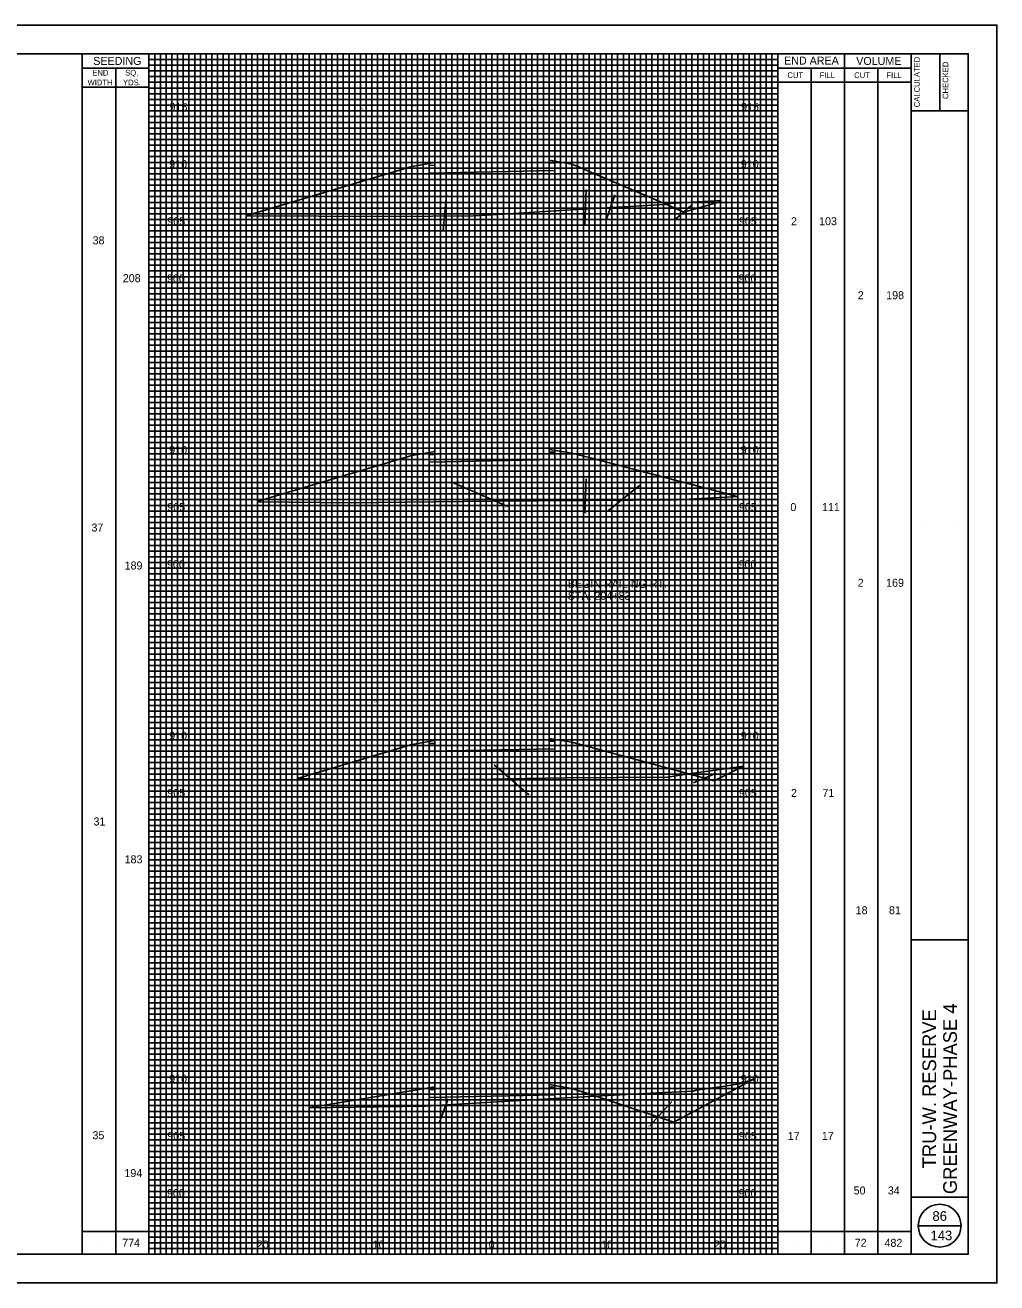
# Model space of a CAD drawing. Extents: x -73 to 160, y -2 to 1877.
# Drawn here: x 75 to 160, y 1377.5 to 1487.5 of the extents above; entities that cross this region are included whole.
import ezdxf

# ---------------------------------------------------------------- set-up
doc = ezdxf.new("R2010")
doc.units = 0
for name, color, linetype in [('DR_P_Flood_Boundary', 7, 'Continuous'), ('GK_Cells', 7, 'Continuous'), ('RD_X_Fence', 7, 'Continuous'), ('TX_X_5', 7, 'Continuous'), ('UT_P_Water_Cells', 7, 'Continuous'), ('XS_P_Pavt_Layers', 7, 'Continuous'), ('XS_P_Pavt_Surface', 7, 'Continuous'), ('XS_X_Ground_Line', 7, 'Continuous')]:
    doc.layers.add(name, color=color, linetype=linetype)

msp = doc.modelspace()

# ---------------------------------------------------------------- linework, layer by layer
at = {"layer": 'DR_P_Flood_Boundary'}
for p, q in [((90.83, 1380), (90.83, 1485)), ((95.83, 1380), (95.83, 1485)), ((100.83, 1380), (100.83, 1485)), ((105.83, 1380), (105.83, 1485)), ((110.83, 1380), (110.83, 1485)), ((115.83, 1380), (115.83, 1485)), ((120.83, 1380), (120.83, 1485)), ((125.83, 1380), (125.83, 1485)), ((130.83, 1380), (130.83, 1485)), ((135.83, 1380), (135.83, 1485)), ((85.83, 1480), (140.83, 1480)), ((85.83, 1475), (140.83, 1475)), ((85.83, 1470), (140.83, 1470)), ((85.83, 1465), (140.83, 1465)), ((85.83, 1460), (140.83, 1460)), ((85.83, 1455), (140.83, 1455)), ((85.83, 1450), (140.83, 1450)), ((85.83, 1445), (140.83, 1445)), ((85.83, 1440), (140.83, 1440)), ((85.83, 1435), (140.83, 1435)), ((85.83, 1430), (140.83, 1430)), ((85.83, 1425), (140.83, 1425)), ((85.83, 1420), (140.83, 1420)), ((85.83, 1415), (140.83, 1415)), ((85.83, 1410), (140.83, 1410)), ((85.83, 1405), (140.83, 1405)), ((85.83, 1400), (140.83, 1400)), ((85.83, 1395), (140.83, 1395)), ((85.83, 1390), (140.83, 1390)), ((85.83, 1385), (140.83, 1385))]:
    msp.add_line(p, q, dxfattribs=at)
at = {"layer": 'GK_Cells'}
for p, q in [((152.5, 1380), (152.5, 1485)), ((155, 1485), (155, 1480)), ((152.5, 1480), (157.5, 1480)), ((152.5, 1407.5), (157.5, 1407.5)), ((152.5, 1385), (157.5, 1385))]:
    msp.add_line(p, q, dxfattribs=at)
msp.add_lwpolyline([(0, 1485), (157.5, 1485), (157.5, 1380), (0, 1380)], close=True, dxfattribs=at)
at = {"layer": 'RD_X_Fence'}
for p, q in [((108.83, 1475.15), (94.31, 1470.83)), ((110.83, 1475.49), (108.83, 1475.15)), ((110.33, 1475.23), (110.83, 1475.24)), ((110.33, 1474.56), (110.33, 1475.23)), ((122.83, 1475.35), (120.83, 1475.69)), ((120.83, 1475.44), (121.33, 1475.45)), ((121.33, 1475.45), (121.33, 1474.78)), ((123.83, 1474.92), (122.83, 1475.35)), ((121.33, 1474.78), (110.33, 1474.56)), ((123.83, 1471.4), (123.83, 1474.92)), ((124.33, 1474.71), (123.83, 1474.92)), ((123.83, 1474.92), (123.83, 1471.4)), ((124.33, 1471.43), (124.33, 1474.71)), ((130.98, 1471.86), (124.33, 1474.71)), ((124.33, 1474.71), (124.33, 1471.43)), ((124.08, 1473.12), (123.97, 1469.99)), ((111.86, 1472.69), (111.57, 1469.54)), ((124.33, 1471.43), (130.99, 1471.8)), ((126.59, 1472.65), (125.85, 1470.54)), ((135.84, 1472.16), (130.98, 1471.86)), ((130.98, 1471.86), (132.63, 1471.15)), ((132.63, 1471.15), (135.87, 1472.07)), ((123.83, 1471.4), (124.33, 1471.43)), ((133.27, 1471.73), (131.93, 1470.57)), ((108.83, 1449.87), (95.37, 1445.86)), ((110.83, 1450.2), (108.83, 1449.87)), ((110.33, 1449.94), (110.83, 1449.95)), ((110.33, 1449.28), (110.33, 1449.94)), ((122.83, 1450.07), (120.83, 1450.4)), ((120.83, 1450.15), (121.33, 1450.16)), ((121.33, 1450.16), (121.33, 1449.5)), ((123.83, 1449.81), (122.83, 1450.07)), ((123.83, 1445.92), (123.83, 1449.81)), ((124.33, 1449.68), (123.83, 1449.81)), ((123.83, 1449.81), (123.83, 1445.92)), ((121.33, 1449.5), (110.33, 1449.28)), ((124.33, 1445.92), (124.33, 1449.68)), ((137.27, 1446.28), (124.33, 1449.68)), ((124.33, 1449.68), (124.33, 1445.92)), ((124.08, 1447.83), (123.97, 1444.81)), ((112.32, 1447.53), (117.22, 1445.41)), ((128.75, 1447.24), (126.04, 1445.06)), ((123.83, 1445.92), (124.33, 1445.92)), ((124.33, 1445.92), (132.05, 1445.98)), ((132.05, 1445.98), (137.27, 1446.28)), ((108.83, 1424.59), (98.83, 1421.61)), ((110.83, 1424.92), (108.83, 1424.59)), ((110.33, 1424.66), (110.83, 1424.67)), ((110.33, 1424), (110.33, 1424.66)), ((122.83, 1424.79), (120.83, 1425.12)), ((120.83, 1424.87), (121.33, 1424.88)), ((121.33, 1424.88), (121.33, 1424.22)), ((133.05, 1422.01), (122.83, 1424.79)), ((121.33, 1424.22), (110.33, 1424)), ((116.03, 1422.81), (119.05, 1420.18)), ((137.83, 1422.7), (133.05, 1422.01)), ((135.26, 1421.41), (137.83, 1422.7)), ((133.05, 1422.01), (135.26, 1421.41)), ((135.38, 1422.04), (133.45, 1421.22)), ((122.83, 1394.51), (120.83, 1394.85)), ((131.75, 1391.54), (138.83, 1395.37)), ((110.83, 1394.65), (99.79, 1392.8)), ((110.33, 1394.39), (110.83, 1394.4)), ((110.33, 1393.72), (110.33, 1394.39)), ((121.33, 1393.94), (110.33, 1393.72)), ((120.83, 1394.6), (121.33, 1394.61)), ((121.33, 1394.61), (121.33, 1393.94)), ((124.92, 1393.82), (122.83, 1394.51)), ((124.92, 1393.82), (131.75, 1391.54)), ((112.01, 1393.58), (111.25, 1391.54)), ((131.56, 1393.36), (129.63, 1391.24))]:
    msp.add_line(p, q, dxfattribs=at)
for points in [[(110.83, 1475.24), (110.83, 1475.38), (110.83, 1475.49)], [(120.83, 1475.69), (120.83, 1475.58), (120.83, 1475.44)], [(130.99, 1471.8), (130.98, 1471.86)], [(135.87, 1472.07), (135.84, 1472.16)], [(94.31, 1470.83), (107.04, 1470.75), (114.22, 1470.83), (115.83, 1470.92), (121.43, 1471.27), (123.83, 1471.4)], [(110.83, 1449.95), (110.83, 1450.1), (110.83, 1450.2)], [(120.83, 1450.4), (120.83, 1450.3), (120.83, 1450.15)], [(95.37, 1445.86), (95.39, 1445.8)], [(95.39, 1445.8), (103.51, 1445.73), (110.75, 1445.82), (115.83, 1445.86), (123.83, 1445.92)], [(110.83, 1424.67), (110.83, 1424.82), (110.83, 1424.92)], [(120.83, 1425.12), (120.83, 1425.02), (120.83, 1424.87)], [(98.83, 1421.61), (104.77, 1421.44), (115.83, 1421.56), (117.1, 1421.58), (122.27, 1421.67), (131.19, 1421.74), (133.05, 1422.01)], [(120.83, 1394.85), (120.83, 1394.74), (120.83, 1394.6)], [(138.83, 1395.37), (137.7, 1394.93), (136.2, 1394.7), (133.69, 1394.34), (133.45, 1394.27), (129.74, 1394.09), (124.92, 1393.82)], [(99.79, 1392.8), (110.03, 1392.96), (115.83, 1393.29), (124.92, 1393.82)], [(110.83, 1394.4), (110.83, 1394.54), (110.83, 1394.65)]]:
    msp.add_lwpolyline(points, dxfattribs=at)
at = {"layer": 'TX_X_5'}
msp.add_lwpolyline([(-10, 1377.5), (160, 1377.5), (160, 1487.5), (-10, 1487.5)], close=True, dxfattribs=at)
at = {"layer": 'UT_P_Water_Cells'}
for p, q in [((86.33, 1380), (86.33, 1485)), ((86.83, 1380), (86.83, 1485)), ((87.33, 1380), (87.33, 1485)), ((87.83, 1380), (87.83, 1485)), ((88.33, 1380), (88.33, 1485)), ((88.83, 1380), (88.83, 1485)), ((89.33, 1380), (89.33, 1485)), ((89.83, 1380), (89.83, 1485)), ((90.33, 1380), (90.33, 1485)), ((91.33, 1380), (91.33, 1485)), ((91.83, 1380), (91.83, 1485)), ((92.33, 1380), (92.33, 1485)), ((92.83, 1380), (92.83, 1485)), ((93.33, 1380), (93.33, 1485)), ((93.83, 1380), (93.83, 1485)), ((94.33, 1380), (94.33, 1485)), ((94.83, 1380), (94.83, 1485)), ((95.33, 1380), (95.33, 1485)), ((96.33, 1380), (96.33, 1485)), ((96.83, 1380), (96.83, 1485)), ((97.33, 1380), (97.33, 1485)), ((97.83, 1380), (97.83, 1485)), ((98.33, 1380), (98.33, 1485)), ((98.83, 1380), (98.83, 1485)), ((99.33, 1380), (99.33, 1485)), ((99.83, 1380), (99.83, 1485)), ((100.33, 1380), (100.33, 1485)), ((101.33, 1380), (101.33, 1485)), ((101.83, 1380), (101.83, 1485)), ((102.33, 1380), (102.33, 1485)), ((102.83, 1380), (102.83, 1485)), ((103.33, 1380), (103.33, 1485)), ((103.83, 1380), (103.83, 1485)), ((104.33, 1380), (104.33, 1485)), ((104.83, 1380), (104.83, 1485)), ((105.33, 1380), (105.33, 1485)), ((106.33, 1380), (106.33, 1485)), ((106.83, 1380), (106.83, 1485)), ((107.33, 1380), (107.33, 1485)), ((107.83, 1380), (107.83, 1485)), ((108.33, 1380), (108.33, 1485)), ((108.83, 1380), (108.83, 1485)), ((109.33, 1380), (109.33, 1485)), ((109.83, 1380), (109.83, 1485)), ((110.33, 1380), (110.33, 1485)), ((111.33, 1380), (111.33, 1485)), ((111.83, 1380), (111.83, 1485)), ((112.33, 1380), (112.33, 1485)), ((112.83, 1380), (112.83, 1485)), ((113.33, 1380), (113.33, 1485)), ((113.83, 1380), (113.83, 1485)), ((114.33, 1380), (114.33, 1485)), ((114.83, 1380), (114.83, 1485)), ((115.33, 1380), (115.33, 1485)), ((116.33, 1380), (116.33, 1485)), ((116.83, 1380), (116.83, 1485)), ((117.33, 1380), (117.33, 1485)), ((117.83, 1380), (117.83, 1485)), ((118.33, 1380), (118.33, 1485)), ((118.83, 1380), (118.83, 1485)), ((119.33, 1380), (119.33, 1485)), ((119.83, 1380), (119.83, 1485)), ((120.33, 1380), (120.33, 1485)), ((121.33, 1380), (121.33, 1485)), ((121.83, 1380), (121.83, 1485)), ((122.33, 1380), (122.33, 1485)), ((122.83, 1380), (122.83, 1485)), ((123.33, 1380), (123.33, 1485)), ((123.83, 1380), (123.83, 1485)), ((124.33, 1380), (124.33, 1485)), ((124.83, 1380), (124.83, 1485)), ((125.33, 1380), (125.33, 1485)), ((126.33, 1380), (126.33, 1485)), ((126.83, 1380), (126.83, 1485)), ((127.33, 1380), (127.33, 1485)), ((127.83, 1380), (127.83, 1485)), ((128.33, 1380), (128.33, 1485)), ((128.83, 1380), (128.83, 1485)), ((129.33, 1380), (129.33, 1485)), ((129.83, 1380), (129.83, 1485)), ((130.33, 1380), (130.33, 1485)), ((131.33, 1380), (131.33, 1485)), ((131.83, 1380), (131.83, 1485)), ((132.33, 1380), (132.33, 1485)), ((132.83, 1380), (132.83, 1485)), ((133.33, 1380), (133.33, 1485)), ((133.83, 1380), (133.83, 1485)), ((134.33, 1380), (134.33, 1485)), ((134.83, 1380), (134.83, 1485)), ((135.33, 1380), (135.33, 1485)), ((136.33, 1380), (136.33, 1485)), ((136.83, 1380), (136.83, 1485)), ((137.33, 1380), (137.33, 1485)), ((137.83, 1380), (137.83, 1485)), ((138.33, 1380), (138.33, 1485)), ((138.83, 1380), (138.83, 1485)), ((139.33, 1380), (139.33, 1485)), ((139.83, 1380), (139.83, 1485)), ((140.33, 1380), (140.33, 1485)), ((85.83, 1484.5), (140.83, 1484.5)), ((85.83, 1484), (140.83, 1484)), ((85.83, 1483.5), (140.83, 1483.5)), ((85.83, 1483), (140.83, 1483)), ((85.83, 1482.5), (140.83, 1482.5)), ((85.83, 1482), (140.83, 1482)), ((85.83, 1481.5), (140.83, 1481.5)), ((85.83, 1481), (140.83, 1481)), ((85.83, 1480.5), (140.83, 1480.5)), ((85.83, 1479.5), (140.83, 1479.5)), ((85.83, 1479), (140.83, 1479)), ((85.83, 1478.5), (140.83, 1478.5)), ((85.83, 1478), (140.83, 1478)), ((85.83, 1477.5), (140.83, 1477.5)), ((85.83, 1477), (140.83, 1477)), ((85.83, 1476.5), (140.83, 1476.5)), ((85.83, 1476), (140.83, 1476)), ((85.83, 1475.5), (140.83, 1475.5)), ((85.83, 1474.5), (140.83, 1474.5)), ((85.83, 1474), (140.83, 1474)), ((85.83, 1473.5), (140.83, 1473.5)), ((85.83, 1473), (140.83, 1473)), ((85.83, 1472.5), (140.83, 1472.5)), ((85.83, 1472), (140.83, 1472)), ((85.83, 1471.5), (140.83, 1471.5)), ((85.83, 1471), (140.83, 1471)), ((85.83, 1470.5), (140.83, 1470.5)), ((85.83, 1469.5), (140.83, 1469.5)), ((85.83, 1469), (140.83, 1469)), ((85.83, 1468.5), (140.83, 1468.5)), ((85.83, 1468), (140.83, 1468)), ((85.83, 1467.5), (140.83, 1467.5)), ((85.83, 1467), (140.83, 1467)), ((85.83, 1466.5), (140.83, 1466.5)), ((85.83, 1466), (140.83, 1466)), ((85.83, 1465.5), (140.83, 1465.5)), ((85.83, 1464.5), (140.83, 1464.5)), ((85.83, 1464), (140.83, 1464)), ((85.83, 1463.5), (140.83, 1463.5)), ((85.83, 1463), (140.83, 1463)), ((85.83, 1462.5), (140.83, 1462.5)), ((85.83, 1462), (140.83, 1462)), ((85.83, 1461.5), (140.83, 1461.5)), ((85.83, 1461), (140.83, 1461)), ((85.83, 1460.5), (140.83, 1460.5)), ((85.83, 1459.5), (140.83, 1459.5)), ((85.83, 1459), (140.83, 1459)), ((85.83, 1458.5), (140.83, 1458.5)), ((85.83, 1458), (140.83, 1458)), ((85.83, 1457.5), (140.83, 1457.5)), ((85.83, 1457), (140.83, 1457)), ((85.83, 1456.5), (140.83, 1456.5)), ((85.83, 1456), (140.83, 1456)), ((85.83, 1455.5), (140.83, 1455.5)), ((85.83, 1454.5), (140.83, 1454.5)), ((85.83, 1454), (140.83, 1454)), ((85.83, 1453.5), (140.83, 1453.5)), ((85.83, 1453), (140.83, 1453)), ((85.83, 1452.5), (140.83, 1452.5)), ((85.83, 1452), (140.83, 1452)), ((85.83, 1451.5), (140.83, 1451.5)), ((85.83, 1451), (140.83, 1451)), ((85.83, 1450.5), (140.83, 1450.5)), ((85.83, 1449.5), (140.83, 1449.5)), ((85.83, 1449), (140.83, 1449)), ((85.83, 1448.5), (140.83, 1448.5)), ((85.83, 1448), (140.83, 1448)), ((85.83, 1447.5), (140.83, 1447.5)), ((85.83, 1447), (140.83, 1447)), ((85.83, 1446.5), (140.83, 1446.5)), ((85.83, 1446), (140.83, 1446)), ((85.83, 1445.5), (140.83, 1445.5)), ((85.83, 1444.5), (140.83, 1444.5)), ((85.83, 1444), (140.83, 1444)), ((85.83, 1443.5), (140.83, 1443.5)), ((85.83, 1443), (140.83, 1443)), ((85.83, 1442.5), (140.83, 1442.5)), ((85.83, 1442), (140.83, 1442)), ((85.83, 1441.5), (140.83, 1441.5)), ((85.83, 1441), (140.83, 1441)), ((85.83, 1440.5), (140.83, 1440.5)), ((85.83, 1439.5), (140.83, 1439.5)), ((85.83, 1439), (140.83, 1439)), ((85.83, 1438.5), (140.83, 1438.5)), ((85.83, 1438), (140.83, 1438)), ((85.83, 1437.5), (140.83, 1437.5)), ((85.83, 1437), (140.83, 1437)), ((85.83, 1436.5), (140.83, 1436.5)), ((85.83, 1436), (140.83, 1436)), ((85.83, 1435.5), (140.83, 1435.5)), ((85.83, 1434.5), (140.83, 1434.5)), ((85.83, 1434), (140.83, 1434)), ((85.83, 1433.5), (140.83, 1433.5)), ((85.83, 1433), (140.83, 1433)), ((85.83, 1432.5), (140.83, 1432.5)), ((85.83, 1432), (140.83, 1432)), ((85.83, 1431.5), (140.83, 1431.5)), ((85.83, 1431), (140.83, 1431)), ((85.83, 1430.5), (140.83, 1430.5)), ((85.83, 1429.5), (140.83, 1429.5)), ((85.83, 1429), (140.83, 1429)), ((85.83, 1428.5), (140.83, 1428.5)), ((85.83, 1428), (140.83, 1428)), ((85.83, 1427.5), (140.83, 1427.5)), ((85.83, 1427), (140.83, 1427)), ((85.83, 1426.5), (140.83, 1426.5)), ((85.83, 1426), (140.83, 1426)), ((85.83, 1425.5), (140.83, 1425.5)), ((85.83, 1424.5), (140.83, 1424.5)), ((85.83, 1424), (140.83, 1424)), ((85.83, 1423.5), (140.83, 1423.5)), ((85.83, 1423), (140.83, 1423)), ((85.83, 1422.5), (140.83, 1422.5)), ((85.83, 1422), (140.83, 1422)), ((85.83, 1421.5), (140.83, 1421.5)), ((85.83, 1421), (140.83, 1421)), ((85.83, 1420.5), (140.83, 1420.5)), ((85.83, 1419.5), (140.83, 1419.5)), ((85.83, 1419), (140.83, 1419)), ((85.83, 1418.5), (140.83, 1418.5)), ((85.83, 1418), (140.83, 1418)), ((85.83, 1417.5), (140.83, 1417.5)), ((85.83, 1417), (140.83, 1417)), ((85.83, 1416.5), (140.83, 1416.5)), ((85.83, 1416), (140.83, 1416)), ((85.83, 1415.5), (140.83, 1415.5)), ((85.83, 1414.5), (140.83, 1414.5)), ((85.83, 1414), (140.83, 1414)), ((85.83, 1413.5), (140.83, 1413.5)), ((85.83, 1413), (140.83, 1413)), ((85.83, 1412.5), (140.83, 1412.5)), ((85.83, 1412), (140.83, 1412)), ((85.83, 1411.5), (140.83, 1411.5)), ((85.83, 1411), (140.83, 1411)), ((85.83, 1410.5), (140.83, 1410.5)), ((85.83, 1409.5), (140.83, 1409.5)), ((85.83, 1409), (140.83, 1409)), ((85.83, 1408.5), (140.83, 1408.5)), ((85.83, 1408), (140.83, 1408)), ((85.83, 1407.5), (140.83, 1407.5)), ((85.83, 1407), (140.83, 1407)), ((85.83, 1406.5), (140.83, 1406.5)), ((85.83, 1406), (140.83, 1406)), ((85.83, 1405.5), (140.83, 1405.5)), ((85.83, 1404.5), (140.83, 1404.5)), ((85.83, 1404), (140.83, 1404)), ((85.83, 1403.5), (140.83, 1403.5)), ((85.83, 1403), (140.83, 1403)), ((85.83, 1402.5), (140.83, 1402.5)), ((85.83, 1402), (140.83, 1402)), ((85.83, 1401.5), (140.83, 1401.5)), ((85.83, 1401), (140.83, 1401)), ((85.83, 1400.5), (140.83, 1400.5)), ((85.83, 1399.5), (140.83, 1399.5)), ((85.83, 1399), (140.83, 1399)), ((85.83, 1398.5), (140.83, 1398.5)), ((85.83, 1398), (140.83, 1398)), ((85.83, 1397.5), (140.83, 1397.5)), ((85.83, 1397), (140.83, 1397)), ((85.83, 1396.5), (140.83, 1396.5)), ((85.83, 1396), (140.83, 1396)), ((85.83, 1395.5), (140.83, 1395.5)), ((85.83, 1394.5), (140.83, 1394.5)), ((85.83, 1394), (140.83, 1394)), ((85.83, 1393.5), (140.83, 1393.5)), ((85.83, 1393), (140.83, 1393)), ((85.83, 1392.5), (140.83, 1392.5)), ((85.83, 1392), (140.83, 1392)), ((85.83, 1391.5), (140.83, 1391.5)), ((85.83, 1391), (140.83, 1391)), ((85.83, 1390.5), (140.83, 1390.5)), ((85.83, 1389.5), (140.83, 1389.5)), ((85.83, 1389), (140.83, 1389)), ((85.83, 1388.5), (140.83, 1388.5)), ((85.83, 1388), (140.83, 1388)), ((85.83, 1387.5), (140.83, 1387.5)), ((85.83, 1387), (140.83, 1387)), ((85.83, 1386.5), (140.83, 1386.5)), ((85.83, 1386), (140.83, 1386)), ((85.83, 1385.5), (140.83, 1385.5)), ((85.83, 1384.5), (140.83, 1384.5)), ((85.83, 1384), (140.83, 1384)), ((85.83, 1383.5), (140.83, 1383.5)), ((85.83, 1383), (140.83, 1383)), ((85.83, 1382.5), (140.83, 1382.5)), ((85.83, 1382), (140.83, 1382)), ((85.83, 1381.5), (140.83, 1381.5)), ((85.83, 1381), (140.83, 1381)), ((85.83, 1380.5), (140.83, 1380.5))]:
    msp.add_line(p, q, dxfattribs=at)
at = {"layer": 'XS_X_Ground_Line'}
for p, q in [((80, 1380), (80, 1485)), ((85.83, 1380), (85.83, 1485)), ((140.83, 1380), (140.83, 1485)), ((146.67, 1380), (146.67, 1485)), ((85.83, 1483.75), (80, 1483.75)), ((82.92, 1380), (82.92, 1483.75)), ((140.83, 1483.75), (152.5, 1483.75)), ((143.75, 1380), (143.75, 1483.75)), ((149.58, 1380), (149.58, 1483.75)), ((85.83, 1482.08), (80, 1482.08)), ((140.83, 1482.5), (152.5, 1482.5)), ((154.6, 1482.52), (154.6, 1482.52)), ((157.1, 1482.52), (157.1, 1482.52)), ((153.75, 1443.75), (153.75, 1443.75)), ((156.26, 1443.75), (156.26, 1443.75)), ((155, 1396.46), (155, 1396.46)), ((155, 1382.92), (155, 1382.92)), ((80, 1382), (85.83, 1382)), ((140.83, 1382), (152.5, 1382)), ((153.12, 1382.5), (156.88, 1382.5)), ((81.46, 1381.03), (81.46, 1381.03)), ((84.37, 1381.03), (84.37, 1381.03)), ((142.29, 1381), (142.29, 1381)), ((145.21, 1381), (145.21, 1381)), ((148.12, 1381), (148.12, 1381)), ((151.04, 1381), (151.04, 1381)), ((155, 1381.22), (155, 1381.22))]:
    msp.add_line(p, q, dxfattribs=at)
msp.add_circle((155, 1382.5), 1.87, dxfattribs=at)

# ---------------------------------------------------------------- texts
at = {"layer": 'RD_X_Fence'}
for s, p in [('15.1', (104.22, 1480.14)), ('2.0', (108.89, 1480.34)), ('2.0', (116.6, 1480.4)), ('10.7', (119.28, 1480.04)), ('4.5', (120.94, 1480.04)), ('89.8', (111.36, 1469.47)), ('1.7', (123.85, 1469.92)), ('11.1', (125.72, 1470.47)), ('2.1', (131.81, 1470.5)), ('14.3', (100.09, 1455.82)), ('2.0', (106.02, 1456.02)), ('2.0', (117.41, 1455.36)), ('14.9', (119.75, 1455.36)), ('84.0', (117, 1445.34)), ('1.9', (123.85, 1444.74)), ('25.3', (125.84, 1444.99)), ('10.4', (105.51, 1428.28)), ('2.0', (108.78, 1428.32)), ('2.0', (119.49, 1427.99)), ('12.9', (122.43, 1427.99)), ('2.2', (133.3, 1421.15)), ('70.8', (118.84, 1420.11)), ('2.0', (116.86, 1399.08)), ('9.4', (119.51, 1398.73)), ('8.1', (121.76, 1398.69)), ('11.2', (106.98, 1397.24)), ('16.9', (111.07, 1391.47)), ('17.2', (129.46, 1391.17))]:
    msp.add_text(s, height=0.14, dxfattribs=at).set_placement(p)
at = {"layer": 'XS_P_Pavt_Layers'}
for s, p in [('86', (154.37, 1382.92)), ('143', (154.2, 1381.22))]:
    msp.add_text(s, height=0.85, dxfattribs=at).set_placement(p)
at = {"layer": 'XS_P_Pavt_Surface'}
for s, p in [('915', (87.63, 1480)), ('915', (137.63, 1480)), ('910', (87.6, 1475)), ('910', (137.6, 1475)), ('905', (87.44, 1470)), ('905', (137.44, 1470)), ('2', (141.99, 1470)), ('103', (144.45, 1470)), ('38', (80.9, 1468.33)), ('208', (83.54, 1465.02)), ('900', (87.41, 1465)), ('900', (137.41, 1465)), ('2', (147.83, 1463.53)), ('198', (150.32, 1463.53)), ('910', (87.6, 1450)), ('910', (137.6, 1450)), ('905', (87.44, 1445)), ('905', (137.44, 1445)), ('0', (141.94, 1445)), ('111', (144.7, 1445)), ('37', (80.8, 1443.21)), ('189', (83.7, 1439.89)), ('900', (87.41, 1440)), ('900', (137.41, 1440)), ('BEGIN RAILING RT.', (122.46, 1438.29)), ('2', (147.83, 1438.38)), ('169', (150.31, 1438.38)), ('STA. 204+83', (122.46, 1437.24)), ('910', (87.6, 1425)), ('910', (137.6, 1425)), ('905', (87.44, 1420)), ('905', (137.44, 1420)), ('2', (141.99, 1420)), ('71', (144.74, 1420)), ('31', (80.98, 1417.5)), ('183', (83.7, 1414.19)), ('18', (147.65, 1409.74)), ('81', (150.56, 1409.74)), ('910', (87.6, 1395)), ('910', (137.6, 1395)), ('35', (80.89, 1390.06)), ('905', (87.44, 1390)), ('905', (137.44, 1390)), ('17', (141.71, 1390)), ('17', (144.69, 1390)), ('194', (83.68, 1386.75)), ('900', (87.41, 1385)), ('900', (137.41, 1385)), ('50', (147.47, 1385.23)), ('34', (150.46, 1385.23)), ('774', (83.49, 1380.65)), ('20', (95.26, 1380.5)), ('10', (105.39, 1380.5)), ('0', (115.55, 1380.5)), ('0', (115.55, 1380.5)), ('10', (125.39, 1380.5)), ('20', (135.26, 1380.5)), ('72', (147.57, 1380.65)), ('482', (150.17, 1380.65))]:
    msp.add_text(s, height=0.7, dxfattribs=at).set_placement(p)
for s, p in [('GREENWAY-PHASE 4', (156.51, 1385.26)), ('TRU-W. RESERVE', (154.69, 1387.52))]:
    msp.add_text(s, height=1.2, rotation=90, dxfattribs=at).set_placement(p)
at = {"layer": 'XS_X_Ground_Line'}
for s, height, p in [('SEEDING', 0.7, (80.96, 1484.02)), ('END AREA', 0.7, (141.39, 1484.05)), ('VOLUME', 0.7, (147.7, 1484.02)), ('END', 0.5, (80.87, 1483.09)), ('SQ.', 0.5, (83.75, 1483.09)), ('CUT', 0.5, (141.68, 1482.87)), ('FILL', 0.5, (144.5, 1482.87)), ('CUT', 0.5, (147.52, 1482.87)), ('FILL', 0.5, (150.34, 1482.87)), ('WIDTH', 0.5, (80.46, 1482.24)), ('YDS.', 0.5, (83.56, 1482.24)), ('143', 0.85, (154.2, 1381.22))]:
    msp.add_text(s, height=height, dxfattribs=at).set_placement(p)
for s, p in [('CALCULATED', (153.26, 1480.32)), ('CHECKED', (155.76, 1481.04))]:
    msp.add_text(s, height=0.5, rotation=90, dxfattribs=at).set_placement(p)

doc.saveas('drawing.dxf')
